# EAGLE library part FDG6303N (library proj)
Fairchild dual N fet
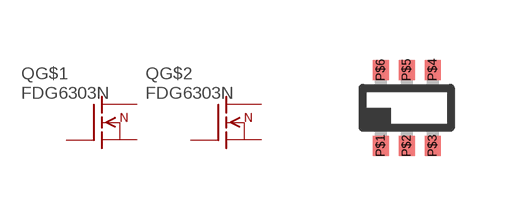
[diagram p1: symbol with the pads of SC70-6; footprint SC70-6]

Designator prefix Q; gates G$1=FET-DUAL-N G$2=FET-DUAL-N

## FDG6303N  [SC70-6]
P$1  G$1:SN  pas
P$2  G$1:GN  pas
P$3  G$2:DN  pas
P$4  G$2:SN  pas
P$5  G$2:GN  pas
P$6  G$1:DN  pas

## Footprint SC70-6 (pad centres in mm)
Fairchild SC70-6
smd 0.4 x 0.5: P$1 -0.65,-0.95; P$2 0,-0.95; P$3 0.65,-0.95; P$4 0.65,0.95; P$5 0,0.95; P$6 -0.65,0.95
